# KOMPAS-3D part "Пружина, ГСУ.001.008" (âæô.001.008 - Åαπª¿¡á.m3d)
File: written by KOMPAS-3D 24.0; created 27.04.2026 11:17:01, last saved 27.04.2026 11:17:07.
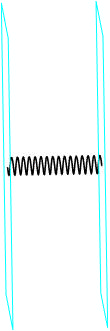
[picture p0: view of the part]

Document properties: Автор: User7; Полное имя файла: C:\Users\User7\Desktop\олимп\ГСУ.001.008 - Пружина.m3d

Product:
- Part/product: Пружина  | designation ГСУ.001.008
    Масса: 0.00001

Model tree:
1. Спираль рабочих витков
     Шаг = 1.00625; Диаметр 2 = 10
2. Сечение проволоки  (labels: Смещенная плоскость 1)
     Толщина стенки 1 = 0.01; Толщина стенки 2 = 0.01; Длина траектории = 156.653; Шаг = 0.1; Диаметр 2 = 10; Шаг = 0.1; Направление навивки = 139296; Диаметр 2 = 10; Толщина стенки 1 = 0.01; Толщина стенки 2 = 0.01; Длина траектории = 9.73945
3. Сечение проволоки 2
     Толщина стенки 1 = 0.01; Толщина стенки 2 = 0.01; Длина траектории = 9.73945
4. Секущая плоскость 1  (labels: Сечение плоскостью 1)
5. Секущая плоскость 2  (labels: Сечение плоскостью 2)
6. Плоскость для сопряжений 1
7. Плоскость для сопряжений 2
8. Пружина

Expressions: L-(d+2*n2*d-2*n3*d); 0.5*d+(n2*d-n3*d); L-(d+2*n2*d-2*n3*d)+0.5*d+(n2*d-n3*d); (D1-d)/2
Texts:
  ГСУ.001.008
  Расстояние от центра до окружности
  Направление навивки (1 - правое; 0 - левое)
  Наружный диаметр пружины, мм
  Диаметр проволоки, мм
  Число рабочих витков
  Число поджатых витков с одной стороны
  Число обработанных витков с одной стороны
  Кинематическая операция для рабочих витков
  Спираль первого поджатого витка
  Спираль второго поджатого витка
  Кинематическая операция для первого поджатого витка
  Кинематическая операция для второго поджатого витка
